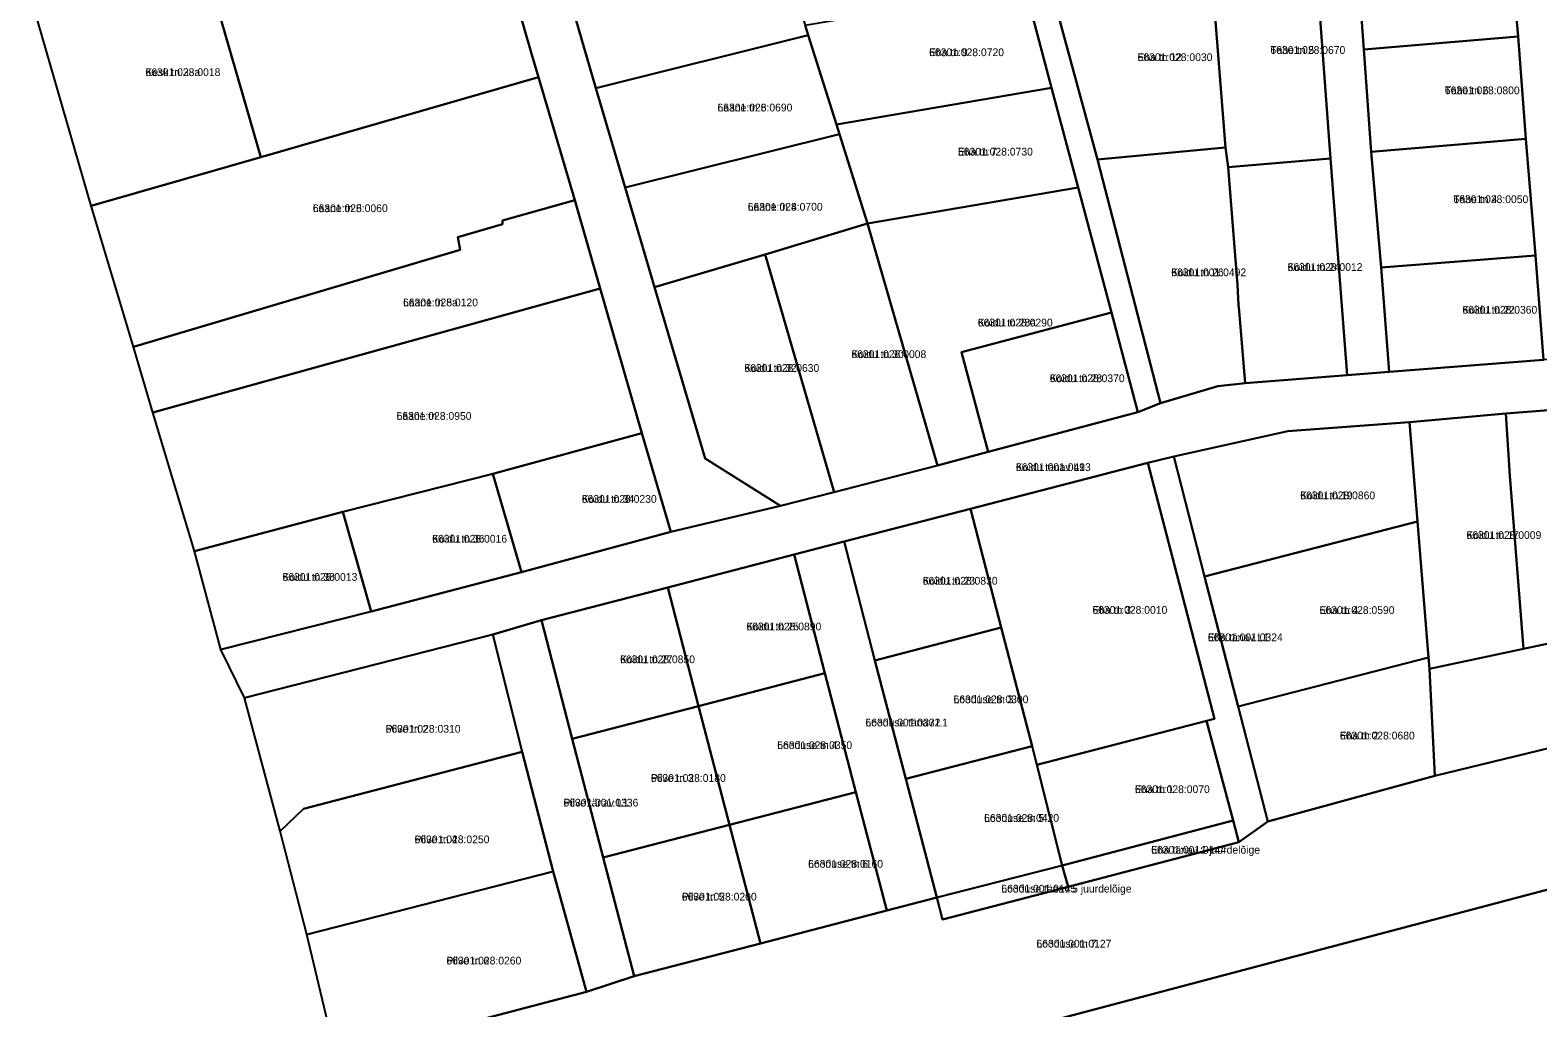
# Model space of a CAD drawing. Extents: x 632278 to 636344, y 6578401 to 6583362.
# Drawn here: x 632850.1 to 633142, y 6581990.5 to 6582179.7 of the extents above; entities that cross this region are included whole.
import ezdxf

# ---------------------------------------------------------------- set-up
doc = ezdxf.new("R2010")
doc.units = 0
for name, color, linetype in [('L_AADRESS', 7, 'Continuous'), ('PIIR', 7, 'Continuous'), ('TUNNUS', 7, 'Continuous')]:
    doc.layers.add(name, color=color, linetype=linetype)

msp = doc.modelspace()

# ---------------------------------------------------------------- linework, layer by layer
at = {"layer": 'PIIR'}
for points in [[(633083.84, 6582282.22), (633091.83, 6582282.57), (633099.63, 6582238.17), (633105.06, 6582208.24), (633106.71, 6582198.2), (633108.33, 6582175.99), (633109.76, 6582156.19), (633111.72, 6582133.82), (633113.23, 6582113.59), (633105.08, 6582112.97), (633101.88, 6582154.89), (633098.72, 6582197.72), (633093.73, 6582226.74), (633088.38, 6582255.59)], [(633023.24, 6582242.75), (633015.25, 6582273.48), (633025.23, 6582275.04), (633032.69, 6582246.19), (633039.78, 6582218.84), (633047.5, 6582188.99), (633056.74, 6582154.68), (633068.96, 6582107.55), (633064.58, 6582105.78), (633059.45, 6582125.11), (633053.02, 6582149.29), (633047.89, 6582168.61), (633042.75, 6582187.94), (633040.99, 6582193.04), (633029.03, 6582239.07)], [(632882.98, 6582195.99), (632889.18, 6582197.84), (632910, 6582204.12), (632936.71, 6582211.65), (632947.12, 6582175.45), (632948.55, 6582170.62), (632894.77, 6582155.17)], [(633141.54, 6582136.13), (633139.71, 6582158.69), (633138.24, 6582178.49), (633136.14, 6582201.28), (633174.79, 6582203.63), (633181.02, 6582118.81), (633143.13, 6582115.89)], [(633106.71, 6582198.2), (633122.89, 6582199.92), (633123.65, 6582200.81), (633136.14, 6582201.28), (633138.24, 6582178.49), (633108.33, 6582175.99)], [(632850.11, 6582186.65), (632877.03, 6582194.25), (632882.98, 6582195.99), (632894.77, 6582155.17), (632888.7, 6582153.44), (632861.94, 6582145.76)], [(633000.15, 6582180.73), (633000.77, 6582178.76), (632959.63, 6582168.5), (632954.09, 6582187.66), (632994.63, 6582197.57)], [(633081.55, 6582157.04), (633078.59, 6582194.56), (633098.72, 6582197.72), (633101.88, 6582154.89), (633082.07, 6582153.21)], [(633072.97, 6582193.64), (633078.59, 6582194.56), (633081.55, 6582157.04), (633056.74, 6582154.68), (633047.5, 6582188.99)], [(633000.77, 6582178.76), (633000.15, 6582180.73), (633019.64, 6582183.99), (633042.75, 6582187.94), (633047.89, 6582168.61), (633006.21, 6582161.49)], [(632959.63, 6582168.5), (633000.77, 6582178.76), (633006.21, 6582161.49), (633006.82, 6582159.59), (632965.31, 6582149.26)], [(633108.33, 6582175.99), (633138.24, 6582178.49), (633139.71, 6582158.69), (633109.76, 6582156.19)], [(632870.14, 6582118.41), (632861.94, 6582145.76), (632888.7, 6582153.44), (632894.77, 6582155.17), (632948.55, 6582170.62), (632955.55, 6582146.83), (632941.56, 6582142.87), (632941.59, 6582142.21), (632932.94, 6582139.64), (632933.37, 6582137.19)], [(633006.82, 6582159.59), (633006.21, 6582161.49), (633047.89, 6582168.61), (633053.02, 6582149.29), (633012.26, 6582142.33)], [(632965.31, 6582149.26), (633006.82, 6582159.59), (633012.26, 6582142.33), (632992.44, 6582136.34), (632970.99, 6582130.02)], [(633139.71, 6582158.69), (633141.54, 6582136.13), (633111.72, 6582133.82), (633109.76, 6582156.19)], [(633068.96, 6582107.55), (633056.74, 6582154.68), (633081.55, 6582157.04), (633082.07, 6582153.21), (633083.9, 6582130.44), (633084.08, 6582126.48), (633084.22, 6582125.4), (633085.37, 6582111.42), (633080.05, 6582110.83)], [(633101.88, 6582154.89), (633105.08, 6582112.97), (633085.37, 6582111.42), (633084.22, 6582125.4), (633084.08, 6582126.48), (633083.9, 6582130.44), (633082.07, 6582153.21)], [(633059.45, 6582125.11), (633030.45, 6582117.42), (633035.58, 6582098.09), (633025.77, 6582095.48), (633012.26, 6582142.33), (633053.02, 6582149.29)], [(632873.89, 6582105.74), (632870.14, 6582118.41), (632933.37, 6582137.19), (632932.94, 6582139.64), (632941.59, 6582142.21), (632941.56, 6582142.87), (632955.55, 6582146.83), (632960.46, 6582129.75)], [(632992.44, 6582136.34), (633012.26, 6582142.33), (633025.77, 6582095.48), (633005.78, 6582090.31)], [(633005.78, 6582090.31), (632995.42, 6582087.64), (632980.8, 6582096.79), (632970.99, 6582130.02), (632992.44, 6582136.34)], [(633111.72, 6582133.82), (633141.54, 6582136.13), (633143.13, 6582115.89), (633113.23, 6582113.59)], [(632873.89, 6582105.74), (632960.46, 6582129.75), (632968.55, 6582101.7), (632939.71, 6582093.84), (632910.63, 6582086.47), (632881.91, 6582078.87)], [(633030.45, 6582117.42), (633059.45, 6582125.11), (633064.58, 6582105.78), (633035.58, 6582098.09)], [(633117.17, 6582103.87), (633135.84, 6582105.56), (633136.6, 6582093.43), (633139.23, 6582059.98), (633121.02, 6582056.08), (633120.84, 6582058.32), (633118.72, 6582084.63)], [(633136.6, 6582093.43), (633135.84, 6582105.56), (633154.04, 6582106.98), (633157.36, 6582063.86), (633139.23, 6582059.98)], [(633071.53, 6582097.18), (633093.64, 6582102.08), (633117.17, 6582103.87), (633118.72, 6582084.63), (633077.51, 6582073.98)], [(632939.71, 6582093.84), (632968.55, 6582101.7), (632974.17, 6582082.62), (632945.23, 6582074.79)], [(633066.52, 6582096), (633071.53, 6582097.18), (633077.51, 6582073.98), (633084.01, 6582048.81), (633089.74, 6582026.54), (633084.12, 6582022.51), (633083.01, 6582026.72), (633077.9, 6582046.05), (633079.4, 6582046.44)], [(632939.71, 6582093.84), (632945.23, 6582074.79), (632916.16, 6582067.22), (632910.63, 6582086.47)], [(633044.11, 6582041.12), (633038.14, 6582064.1), (633032.16, 6582087.07), (633066.52, 6582096), (633079.4, 6582046.44), (633077.91, 6582046.05), (633045.04, 6582037.51)], [(632881.91, 6582078.87), (632910.63, 6582086.47), (632916.16, 6582067.22), (632887.06, 6582059.81)], [(633007.7, 6582080.72), (633032.16, 6582087.07), (633038.14, 6582064.1), (633013.68, 6582057.74)], [(633084.01, 6582048.81), (633077.51, 6582073.98), (633118.72, 6582084.63), (633120.84, 6582058.32)], [(633007.7, 6582080.72), (633013.68, 6582057.74), (633019.65, 6582034.77), (633025.66, 6582011.82), (633015.95, 6582009.28), (633009.98, 6582032.25), (633004, 6582055.23), (632998.02, 6582078.2)], [(632973.57, 6582071.85), (632998.02, 6582078.2), (633004, 6582055.23), (632979.54, 6582048.88)], [(632949.11, 6582065.5), (632973.57, 6582071.85), (632979.54, 6582048.88), (632955.08, 6582042.52)], [(632939.69, 6582062.77), (632949.11, 6582065.5), (632955.08, 6582042.52), (632961.06, 6582019.55), (632967.03, 6581996.57), (632957.8, 6581993.58), (632951.4, 6582016.86), (632945.4, 6582040.01)], [(633122.08, 6582035.35), (633121.02, 6582056.08), (633139.23, 6582059.98), (633157.36, 6582063.86), (633163.01, 6582065.06), (633164.6, 6582045.69)], [(632898.49, 6582024.68), (632891.61, 6582050.51), (632939.69, 6582062.77), (632945.4, 6582040.01), (632903.04, 6582029)], [(633013.68, 6582057.74), (633038.14, 6582064.1), (633044.11, 6582041.12), (633019.65, 6582034.77)], [(633084.01, 6582048.81), (633120.84, 6582058.32), (633121.02, 6582056.08), (633122.08, 6582035.35), (633089.75, 6582026.53)], [(632979.54, 6582048.88), (633004, 6582055.23), (633009.98, 6582032.25), (632985.52, 6582025.9)], [(632909.35, 6581980.86), (632957.8, 6581993.58), (632967.03, 6581996.57), (632991.49, 6582002.93), (633015.95, 6582009.28), (633025.66, 6582011.82), (633026.77, 6582007.57), (633051.07, 6582013.9), (633084.12, 6582022.51), (633089.74, 6582026.54), (633122.08, 6582035.35), (633164.6, 6582045.69), (633185.49, 6582050.79), (633188.66, 6582025.2), (633111.47, 6582004.79), (632917.6, 6581953.49)], [(632961.06, 6582019.55), (632955.08, 6582042.52), (632979.54, 6582048.88), (632985.52, 6582025.9)], [(633049.94, 6582018.02), (633045.04, 6582037.51), (633077.9, 6582046.05), (633083.01, 6582026.72)], [(633019.65, 6582034.77), (633044.11, 6582041.12), (633045.04, 6582037.51), (633049.94, 6582018.02), (633025.66, 6582011.82)], [(632945.4, 6582040.01), (632951.4, 6582016.86), (632903.7, 6582004.64), (632898.49, 6582024.68), (632903.04, 6582029)], [(632985.52, 6582025.9), (633009.98, 6582032.25), (633015.95, 6582009.28), (632991.49, 6582002.93)], [(633051.07, 6582013.9), (633049.94, 6582018.02), (633083.01, 6582026.72), (633084.12, 6582022.51)], [(632961.06, 6582019.55), (632985.52, 6582025.9), (632991.49, 6582002.93), (632967.03, 6581996.57)], [(633026.77, 6582007.57), (633025.66, 6582011.82), (633049.94, 6582018.02), (633051.07, 6582013.9)], [(632909.35, 6581980.86), (632903.7, 6582004.64), (632951.4, 6582016.86), (632957.8, 6581993.58)]]:
    msp.add_lwpolyline(points, close=True, dxfattribs=at)
for points in [[(632954.09, 6582187.66), (632959.63, 6582168.5), (632965.31, 6582149.26), (632970.99, 6582130.02), (632980.8, 6582096.79), (632995.42, 6582087.64), (632974.17, 6582082.62), (632968.55, 6582101.7), (632960.46, 6582129.75), (632955.55, 6582146.83), (632948.55, 6582170.62), (632947.12, 6582175.45), (632936.71, 6582211.65)], [(633730.08, 6582121.51), (633462.58, 6582051.42), (633249.26, 6581995.68), (633111.38, 6581959.61), (632922.41, 6581910.15), (632911.02, 6581915.61), (632904.86, 6581940.22), (632917.6, 6581953.49), (633111.47, 6582004.79), (633188.66, 6582025.2), (633225.56, 6582033.97), (633263.61, 6582043.97), (633285.26, 6582049.62), (633306.37, 6582055.12), (633345.53, 6582065.35), (633379.07, 6582074.94), (633417.92, 6582084.78), (633420.06, 6582085.3), (633443.96, 6582091.45), (633599.55, 6582131.45), (633717.52, 6582162.1), (633843.89, 6582195.39)], [(633154.04, 6582106.98), (633135.84, 6582105.56), (633117.17, 6582103.87), (633093.64, 6582102.08), (633071.53, 6582097.18), (633066.52, 6582096), (633032.16, 6582087.07), (633007.7, 6582080.72), (632998.02, 6582078.2), (632973.57, 6582071.85), (632949.11, 6582065.5), (632939.69, 6582062.77), (632891.61, 6582050.51), (632887.06, 6582059.81), (632916.16, 6582067.22), (632945.23, 6582074.79), (632974.17, 6582082.62), (632995.42, 6582087.64), (633005.78, 6582090.31), (633025.77, 6582095.48), (633035.58, 6582098.09), (633064.58, 6582105.78), (633068.96, 6582107.55), (633080.05, 6582110.83), (633085.37, 6582111.42), (633105.08, 6582112.97), (633113.23, 6582113.59), (633143.13, 6582115.89)]]:
    msp.add_lwpolyline(points, dxfattribs=at)

# ---------------------------------------------------------------- texts
at = {"layer": 'L_AADRESS'}
for s, p in [('Eha tn 9', (633024.16, 6582174.71)), ('Eha tn 12', (633064.52, 6582173.76)), ('Tähe tn 5', (633090.24, 6582175.15)), ('Kesk tn 33a', (632872.44, 6582170.86)), ('Tähe tn 6', (633124.01, 6582167.34)), ('Lääne tn 6', (632983.19, 6582164.01)), ('Eha tn 7', (633029.75, 6582155.47)), ('Lääne tn 5', (632904.84, 6582144.52)), ('Lääne tn 4', (632989.05, 6582144.8)), ('Tähe tn 4', (633125.67, 6582146.26)), ('Koidu tn 24', (633093.57, 6582133.13)), ('Koidu tn 26', (633071.05, 6582132.11)), ('Lääne tn 5a', (632922.31, 6582126.28)), ('Koidu tn 22', (633127.41, 6582124.86)), ('Koidu tn 28a', (633033.59, 6582122.38)), ('Koidu tn 30', (633009.11, 6582116.27)), ('Koidu tn 32', (632988.39, 6582113.59)), ('Koidu tn 28', (633047.52, 6582111.6)), ('Lääne tn 3', (632921.06, 6582104.31)), ('Koidu tänav L1', (633040.96, 6582094.4)), ('Koidu tn 19', (633096.02, 6582088.93)), ('Koidu tn 34', (632956.92, 6582088.24)), ('Koidu tn 36', (632927.95, 6582080.53)), ('Koidu tn 17', (633128.2, 6582081.24)), ('Koidu tn 38', (632898.96, 6582073.14)), ('Koidu tn 23', (633022.92, 6582072.4)), ('Eha tn 3', (633055.78, 6582066.75)), ('Eha tn 4', (633099.77, 6582066.72)), ('Koidu tn 25', (632988.78, 6582063.54)), ('Eha tänav L1', (633078.13, 6582061.45)), ('Koidu tn 27', (632964.33, 6582057.19)), ('Looduse tn 3', (633028.89, 6582049.44)), ('Pilve tn 2', (632918.94, 6582043.73)), ('Looduse tänav L1', (633011.84, 6582044.95)), ('Eha tn 2', (633103.69, 6582042.43)), ('Looduse tn 4', (632994.76, 6582040.57)), ('Pilve tn 3', (632970.3, 6582034.21)), ('Eha tn 1', (633064.01, 6582032.04)), ('Pilve tänav L1', (632953.36, 6582029.44)), ('Looduse tn 5', (633034.82, 6582026.47)), ('Pilve tn 4', (632924.54, 6582022.33)), ('Eha tänav 1 juurdelõige', (633067.16, 6582020.31)), ('Looduse tn 6', (633000.74, 6582017.59)), ('Pilve tn 5', (632976.28, 6582011.24)), ('Looduse tänav 5 juurdelõige', (633038.15, 6582012.79)), ('Looduse tn 7', (633044.95, 6582002.14)), ('Pilve tn 6', (632930.71, 6581998.86))]:
    msp.add_text(s, height=1.5, dxfattribs=at).set_placement(p)
at = {"layer": 'TUNNUS'}
for s, p in [('66301:028:0720', (633024.16, 6582174.71)), ('66301:028:0030', (633064.52, 6582173.76)), ('66301:028:0670', (633090.24, 6582175.15)), ('66301:028:0018', (632872.44, 6582170.86)), ('66301:028:0800', (633124.01, 6582167.34)), ('66301:028:0690', (632983.19, 6582164.01)), ('66301:028:0730', (633029.75, 6582155.47)), ('66301:028:0060', (632904.84, 6582144.52)), ('66301:028:0700', (632989.05, 6582144.8)), ('66301:028:0050', (633125.67, 6582146.26)), ('66301:028:0012', (633093.57, 6582133.13)), ('66301:001:0492', (633071.05, 6582132.11)), ('66301:028:0120', (632922.31, 6582126.28)), ('66301:028:0360', (633127.41, 6582124.86)), ('66301:028:0290', (633033.59, 6582122.38)), ('66301:028:0008', (633009.11, 6582116.27)), ('66301:028:0630', (632988.39, 6582113.59)), ('66301:028:0370', (633047.52, 6582111.6)), ('66301:028:0950', (632921.06, 6582104.31)), ('66301:001:0493', (633040.96, 6582094.4)), ('66301:028:0860', (633096.02, 6582088.93)), ('66301:028:0230', (632956.92, 6582088.24)), ('66301:028:0016', (632927.95, 6582080.53)), ('66301:028:0009', (633128.2, 6582081.24)), ('66301:028:0013', (632898.96, 6582073.14)), ('66301:028:0830', (633022.92, 6582072.4)), ('66301:028:0010', (633055.78, 6582066.75)), ('66301:028:0590', (633099.77, 6582066.72)), ('66301:028:0890', (632988.78, 6582063.54)), ('66301:001:0324', (633078.13, 6582061.45)), ('66301:028:0850', (632964.33, 6582057.19)), ('66301:028:0300', (633028.89, 6582049.44)), ('66301:028:0310', (632918.94, 6582043.73)), ('66301:001:0332', (633011.84, 6582044.95)), ('66301:028:0680', (633103.69, 6582042.43)), ('66301:028:0350', (632994.76, 6582040.57)), ('66301:028:0180', (632970.3, 6582034.21)), ('66301:028:0070', (633064.01, 6582032.04)), ('66301:001:0336', (632953.36, 6582029.44)), ('66301:028:0420', (633034.82, 6582026.47)), ('66301:028:0250', (632924.54, 6582022.33)), ('66301:001:0144', (633067.16, 6582020.31)), ('66301:028:0160', (633000.74, 6582017.59)), ('66301:028:0200', (632976.28, 6582011.24)), ('66301:001:0145', (633038.15, 6582012.79)), ('66301:001:0127', (633044.95, 6582002.14)), ('66301:028:0260', (632930.71, 6581998.86))]:
    msp.add_text(s, height=1.5, dxfattribs=at).set_placement(p)

doc.saveas('drawing.dxf')
